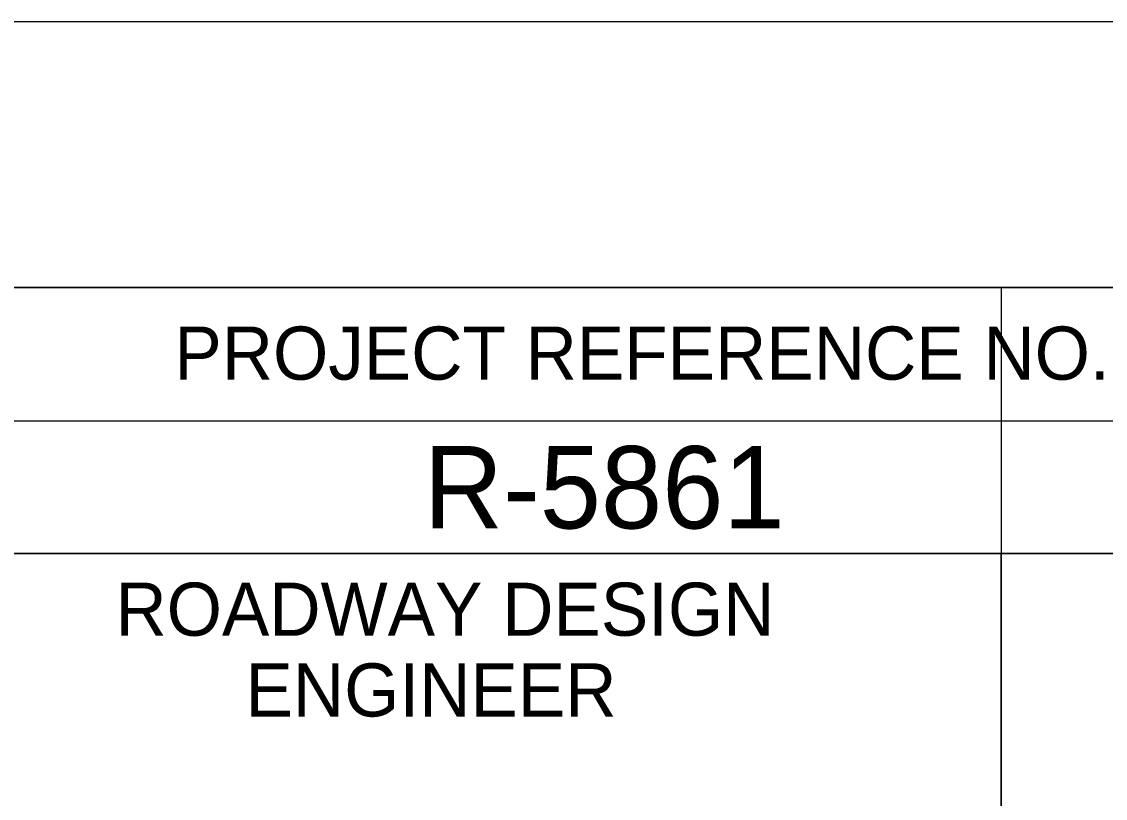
# Model space of a CAD drawing. Extents: x 502400 to 509344, y 448070 to 484209.
# Drawn here: x 507076.9 to 507178.9, y 484135.6 to 484208.7 of the extents above; entities that cross this region are included whole.
import ezdxf

# ---------------------------------------------------------------- set-up
doc = ezdxf.new("R2010")
doc.units = 0
for name, color, linetype in [('Sheet Data Field CELL', 7, 'Continuous'), ('Sheet Layout Profile Border Port 1', 7, 'Continuous'), ('Sheet Plot Border Outside CELL', 7, 'Continuous'), ('Sheet Profile CELL', 7, 'Continuous'), ('Sheet Profile Grid Major CELL', 7, 'Continuous')]:
    doc.layers.add(name, color=color, linetype=linetype)

msp = doc.modelspace()

# ---------------------------------------------------------------- linework, layer by layer
at = {"layer": 'Sheet Layout Profile Border Port 1'}
msp.add_lwpolyline([(506419.08, 484183.71), (507169.08, 484183.71), (507169.08, 483683.71), (506419.08, 483683.71)], close=True, dxfattribs=at)
at = {"layer": 'Sheet Plot Border Outside CELL'}
msp.add_lwpolyline([(505602.08, 483108.71), (507286.08, 483108.71), (507286.08, 484208.71), (505602.08, 484208.71)], close=True, dxfattribs=at)
at = {"layer": 'Sheet Profile CELL'}
for p, q in [((507069.03, 484171.16), (507269.08, 484171.16)), ((507169.08, 484158.66), (507169.08, 484046.21))]:
    msp.add_line(p, q, dxfattribs=at)
for points in [[(507269.08, 484183.71), (505769.08, 484183.71), (505769.08, 483133.71), (507269.08, 483133.71)], [(507069.03, 484183.71), (507269.08, 484183.71), (507269.08, 484158.66), (507069.03, 484158.66)], [(507069.03, 484158.66), (507169.08, 484158.66), (507169.08, 484046.16), (507069.03, 484046.16)], [(507169.08, 484158.66), (507269.08, 484158.66), (507269.08, 484046.16), (507169.08, 484046.16)]]:
    msp.add_lwpolyline(points, close=True, dxfattribs=at)
at = {"layer": 'Sheet Profile Grid Major CELL'}
msp.add_lwpolyline([(506519.08, 483683.71), (506569.08, 483683.71), (506569.08, 484183.71), (506619.08, 484183.71), (506619.08, 483683.71), (506669.08, 483683.71), (506669.08, 484183.71), (506719.08, 484183.71), (506719.08, 483683.71), (506769.08, 483683.71), (506769.08, 484183.71), (506819.08, 484183.71), (506819.08, 483683.71), (506869.08, 483683.71), (506869.08, 484183.71), (506919.08, 484183.71), (506919.08, 483683.71), (506969.08, 483683.71), (506969.08, 484183.71), (507019.08, 484183.71), (507019.08, 483683.71), (507069.08, 483683.71), (507069.08, 484183.71), (507095.38, 484183.71)], dxfattribs=at)

# ---------------------------------------------------------------- texts
at = {"layer": 'Sheet Data Field CELL'}
msp.add_text('R-5861', height=7.75, dxfattribs=at).set_placement((507114.7, 484161.02))
at = {"layer": 'Sheet Profile CELL'}
for s, height, p in [('PROJECT REFERENCE NO.', 5.0001, (507091.24, 484175.02)), ('ROADWAY DESIGN', 5.0001, (507085.69, 484150.92)), ('ENGINEER', 5, (507097.94, 484143.32))]:
    msp.add_text(s, height=height, dxfattribs=at).set_placement(p)

doc.saveas('drawing.dxf')
